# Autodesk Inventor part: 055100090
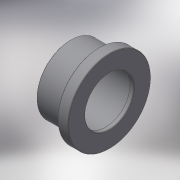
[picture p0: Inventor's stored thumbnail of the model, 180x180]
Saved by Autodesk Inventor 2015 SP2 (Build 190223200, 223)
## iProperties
Created: 2017-10
Part Number: 055100090
Material: Generic
Description: PLASSON FLANGE FLAT AD.-CEM 90
Document SubType Name: Modeling
Designer: KIM
Mass: 174.146 g
Surface Area: 484.55 cm^2
Volume: 174.146 cm^3
Density: 1 g/cm^3
Appearance: Default
Author: KIM
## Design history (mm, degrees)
derived "055100.ipt"
feature "Solid1::055100.ipt"
tag "TaggingFeature1"
body "Solid1"
other parameters: "d0" = 56, "d1" = 105, "d3" = 81, "d4" = 11, "d5" = 51, "d6" = 125, "d8" = 0.9, "E_" = 105, "E_1" = 125, "l_" = 51, "B_" = 11, "H_" = 56
